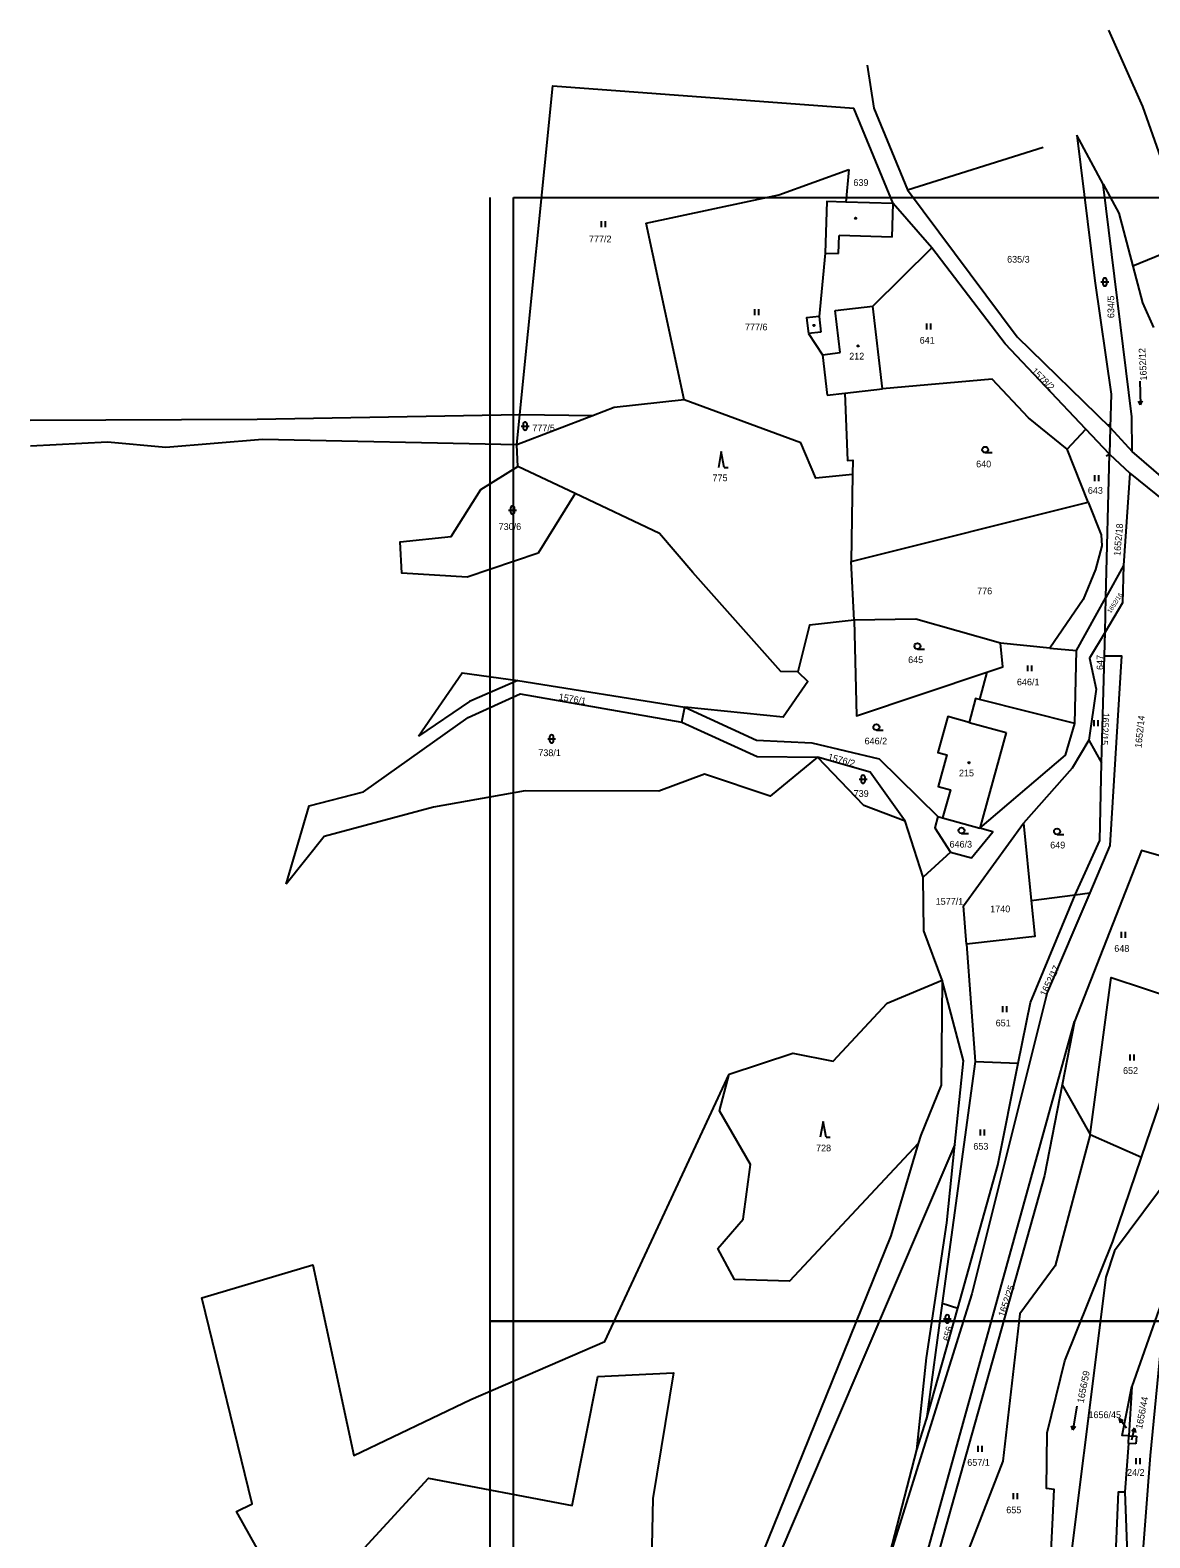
# Model space of a CAD drawing. Extents: x -553916 to -552953, y -1067470 to -1066637.
# Drawn here: x -553916.1 to -553633.4, y -1067154.7 to -1066774 of the extents above; entities that cross this region are included whole.
import ezdxf

# ---------------------------------------------------------------- set-up
doc = ezdxf.new("R2010")
doc.units = 0
for name, color, linetype in [('Hranice parcel', 7, 'Continuous'), ('Parcelní čísla', 7, 'Continuous'), ('Pop  PČ popisy', 7, 'Continuous'), ('Vnitřní kresba', 7, 'Continuous'), ('Vrstva 1', 7, 'Continuous'), ('Značky budov', 7, 'Continuous'), ('Značky kultur', 7, 'Continuous')]:
    doc.layers.add(name, color=color, linetype=linetype)

msp = doc.modelspace()

# ---------------------------------------------------------------- linework, layer by layer
at = {"layer": 'Hranice parcel'}
for p, q in [((-553698.19, -1066817.82), (-553708.14, -1066793.72)), ((-553694.61, -1066814.35), (-553660.35, -1066803.56)), ((-553645.19, -1066812.95), (-553651.89, -1066800.53)), ((-553727.1, -1066815.64), (-553709.46, -1066809.18)), ((-553709.46, -1066809.18), (-553710.17, -1066817.45)), ((-553760.56, -1066822.8), (-553727.1, -1066815.64)), ((-553698.19, -1066817.82), (-553710.17, -1066817.45)), ((-553688.48, -1066828.98), (-553698.19, -1066817.82)), ((-553750.96, -1066867.38), (-553760.56, -1066822.8)), ((-553623.67, -1066827.87), (-553637.71, -1066833.62)), ((-553710.42, -1066865.69), (-553700.89, -1066864.57)), ((-553714.89, -1066866.21), (-553710.42, -1066865.69)), ((-553793.21, -1066878.75), (-553792.44, -1066871.07)), ((-553773.88, -1066871.32), (-553793.21, -1066878.75)), ((-553792.44, -1066871.07), (-553773.88, -1066871.32)), ((-553654.33, -1066879.84), (-553649.57, -1066874.82)), ((-553643.58, -1066881.05), (-553649.57, -1066874.82)), ((-553643.41, -1066874.34), (-553637.93, -1066880.39)), ((-553792.95, -1066884.2), (-553793.21, -1066878.75)), ((-553648.98, -1066893.19), (-553654.33, -1066879.84)), ((-553629.4, -1066887.71), (-553637.93, -1066880.39)), ((-553778.5, -1066891.03), (-553792.95, -1066884.2)), ((-553644.51, -1066917.3), (-553643.58, -1066881.05)), ((-553643.58, -1066881.05), (-553638.51, -1066885.89)), ((-553708.48, -1066886.24), (-553708.86, -1066908.17)), ((-553638.51, -1066885.89), (-553640.1, -1066909.21)), ((-553708.86, -1066908.17), (-553648.98, -1066893.19)), ((-553708.1, -1066923.04), (-553708.86, -1066908.17)), ((-553640.1, -1066909.21), (-553644.51, -1066917.3)), ((-553651.92, -1066930.68), (-553644.51, -1066917.3)), ((-553644.74, -1066926.04), (-553644.51, -1066917.3)), ((-553644.89, -1066931.97), (-553644.74, -1066926.04)), ((-553658.66, -1066930.04), (-553671.16, -1066928.84)), ((-553658.66, -1066930.04), (-553651.92, -1066930.68)), ((-553652.33, -1066949.09), (-553651.92, -1066930.68)), ((-553645.59, -1066958.99), (-553644.89, -1066931.97)), ((-553674.58, -1066936.12), (-553676.4, -1066943.07)), ((-553793.02, -1066938.22), (-553750.82, -1066944.94)), ((-553751.58, -1066948.77), (-553750.82, -1066944.94)), ((-553652.33, -1066949.09), (-553676.4, -1066943.07)), ((-553648.85, -1066953.28), (-553645.59, -1066958.99)), ((-553690.64, -1066987.88), (-553695.17, -1066973.73)), ((-553686.98, -1066972.56), (-553685.74, -1066972.91)), ((-553685.74, -1066972.91), (-553676.37, -1066975.51)), ((-553665.3, -1066974.22), (-553663.36, -1066993.83)), ((-553683.73, -1066981.56), (-553690.64, -1066987.88)), ((-553663.36, -1066993.83), (-553652.32, -1066992.37)), ((-553652.32, -1066992.37), (-553648.57, -1066991.82)), ((-553679.73, -1067004.79), (-553677.51, -1067034.42)), ((-553652.47, -1067024.37), (-553655.53, -1067040.29)), ((-553677.51, -1067034.42), (-553685.85, -1067095.42)), ((-553677.51, -1067034.42), (-553666.64, -1067034.88)), ((-553655.53, -1067040.29), (-553648.45, -1067052.9)), ((-553682.64, -1067055.36), (-553736.85, -1067182.11)), ((-553648.45, -1067052.9), (-553635.52, -1067058.6)), ((-553642.79, -1067079.87), (-553635.52, -1067058.6)), ((-553685.85, -1067095.42), (-553689.85, -1067124.72)), ((-553689.85, -1067124.72), (-553681.91, -1067096.73)), ((-553685.85, -1067095.42), (-553681.91, -1067096.73)), ((-553637.98, -1067116.48), (-553638.7, -1067128.96)), ((-553692.26, -1067132.51), (-553689.85, -1067124.72)), ((-553638.81, -1067130.87), (-553639.7, -1067143.1)), ((-553638.81, -1067130.87), (-553638.7, -1067128.96)), ((-553636.94, -1067130.98), (-553638.81, -1067130.87)), ((-553638.7, -1067128.96), (-553636.8, -1067129.04)), ((-553636.8, -1067129.04), (-553636.94, -1067130.98)), ((-553699.64, -1067161.1), (-553692.26, -1067132.51)), ((-553639.7, -1067143.1), (-553638.95, -1067163.99))]:
    msp.add_line(p, q, dxfattribs=at)
for points in [[(-553643.88, -1066774.03), (-553635.29, -1066793.34), (-553625.66, -1066820.5)], [(-553704.82, -1066782.89), (-553703.1, -1066793.75), (-553694.61, -1066814.35)], [(-553792.44, -1066871.07), (-553784.13, -1066788.1), (-553708.14, -1066793.72)], [(-553651.89, -1066800.53), (-553647.31, -1066837.34), (-553643.19, -1066865.93), (-553643.41, -1066874.34)], [(-553694.61, -1066814.35), (-553666.95, -1066851.46), (-553643.41, -1066874.34)], [(-553637.93, -1066880.39), (-553637.95, -1066871.66), (-553645.19, -1066812.95)], [(-553645.19, -1066812.95), (-553641.24, -1066820.26), (-553637.71, -1066833.62)], [(-553710.17, -1066817.45), (-553715.01, -1066817.3), (-553715.41, -1066830.35), (-553716.91, -1066846.31), (-553720.09, -1066846.68), (-553719.63, -1066850.66)], [(-553700.89, -1066864.57), (-553703.32, -1066843.72), (-553688.48, -1066828.98)], [(-553649.57, -1066874.82), (-553669.94, -1066853.22), (-553688.48, -1066828.98)], [(-553637.71, -1066833.62), (-553635.67, -1066841.32), (-553635.29, -1066842.84), (-553632.51, -1066849.1)], [(-553719.63, -1066850.66), (-553716.09, -1066855.98), (-553714.89, -1066866.21)], [(-553654.33, -1066879.84), (-553664.06, -1066871.9), (-553673.22, -1066862.17), (-553700.89, -1066864.57)], [(-553750.96, -1066867.38), (-553768.66, -1066869.31), (-553773.88, -1066871.32)], [(-553708.48, -1066886.24), (-553717.76, -1066887.14), (-553721.5, -1066878.2), (-553750.96, -1066867.38)], [(-553710.42, -1066865.69), (-553709.75, -1066882.68), (-553708.42, -1066882.64), (-553708.48, -1066886.24)], [(-553916.1, -1066872.49), (-553858.75, -1066872.29), (-553792.44, -1066871.07)], [(-553793.21, -1066878.75), (-553857.42, -1066877.37), (-553881.82, -1066879.37), (-553896.57, -1066878.03), (-553915.98, -1066879.03)], [(-553778.5, -1066891.03), (-553787.89, -1066906.11), (-553805.77, -1066912.16), (-553822.27, -1066911.17), (-553822.69, -1066903.26), (-553809.84, -1066901.91), (-553802.35, -1066890.01), (-553792.95, -1066884.2)], [(-553638.51, -1066885.89), (-553629.69, -1066892.95), (-553626.61, -1066895.43)], [(-553722.33, -1066936.07), (-553726.59, -1066935.94), (-553748.79, -1066910.99), (-553757.18, -1066901.11), (-553778.5, -1066891.03)], [(-553648.98, -1066893.19), (-553645.71, -1066901.42), (-553645.52, -1066904.26), (-553647.18, -1066910.25), (-553650.27, -1066917.79), (-553658.66, -1066930.04)], [(-553640.1, -1066909.21), (-553640.34, -1066918.66), (-553644.74, -1066926.04)], [(-553708.1, -1066923.04), (-553719.33, -1066924.26), (-553722.33, -1066936.07)], [(-553671.16, -1066928.84), (-553692.53, -1066922.74), (-553708.1, -1066923.04)], [(-553708.1, -1066923.04), (-553707.52, -1066947.12), (-553674.58, -1066936.12)], [(-553644.74, -1066926.04), (-553648.66, -1066932.61), (-553646.94, -1066940.41), (-553648.85, -1066953.28)], [(-553674.58, -1066936.12), (-553670.5, -1066934.76), (-553671.16, -1066928.84)], [(-553644.89, -1066931.97), (-553640.62, -1066932.03), (-553643.49, -1066979.92), (-553648.57, -1066991.82)], [(-553818.03, -1066952.27), (-553807.07, -1066936.29), (-553793.02, -1066938.22)], [(-553722.33, -1066936.07), (-553719.8, -1066938.45), (-553726.01, -1066947.52), (-553750.82, -1066944.94)], [(-553793.02, -1066938.22), (-553805.16, -1066943.52), (-553818.03, -1066952.27)], [(-553851.45, -1066989.66), (-553845.69, -1066969.91), (-553831.91, -1066966.35), (-553805.48, -1066947.58), (-553792.42, -1066941.62), (-553751.58, -1066948.77)], [(-553750.82, -1066944.94), (-553732.69, -1066953.28), (-553718.72, -1066954.01), (-553701.74, -1066958), (-553686.98, -1066972.56)], [(-553676.4, -1066943.07), (-553677.43, -1066942.81), (-553679, -1066948.83), (-553684.45, -1066947.32), (-553686.97, -1066956.38), (-553684.65, -1066957.02), (-553686.87, -1066965.02), (-553683.79, -1066965.88), (-553685.74, -1066972.91)], [(-553751.58, -1066948.77), (-553732.58, -1066957.42), (-553717.29, -1066957.56)], [(-553676.37, -1066975.51), (-553654.76, -1066957.08), (-553652.33, -1066949.09)], [(-553648.85, -1066953.28), (-553653.03, -1066960.38), (-553665.3, -1066974.22)], [(-553717.29, -1066957.56), (-553729.27, -1066967.46), (-553745.82, -1066961.92), (-553757.37, -1066966.16), (-553791.09, -1066966.12), (-553814.24, -1066970.19), (-553841.88, -1066977.67), (-553851.45, -1066989.66)], [(-553695.17, -1066973.73), (-553705.64, -1066969.81), (-553717.29, -1066957.56)], [(-553695.17, -1066973.73), (-553704.05, -1066961.37), (-553717.29, -1066957.56)], [(-553652.32, -1066992.37), (-553646.09, -1066978.61), (-553645.59, -1066958.99)], [(-553686.98, -1066972.56), (-553687.7, -1066975.46), (-553683.73, -1066981.56)], [(-553683.73, -1066981.56), (-553678.45, -1066983.01), (-553673.1, -1066976.42), (-553676.37, -1066975.51)], [(-553679.73, -1067004.79), (-553680.45, -1066995.12), (-553665.3, -1066974.22)], [(-553627.02, -1066983.6), (-553635.52, -1066981.16), (-553652.47, -1067024.37)], [(-553623.32, -1066984.67), (-553619.63, -1066996.83), (-553619.56, -1067023.02), (-553621.7, -1067038.64), (-553627.75, -1067062.69), (-553642.34, -1067082.27), (-553644.52, -1067088.87), (-553655.73, -1067178.24), (-553657.73, -1067185.13), (-553660.17, -1067189.87)], [(-553685.87, -1067013.91), (-553690.5, -1067001.43), (-553690.64, -1066987.88)], [(-553648.57, -1066991.82), (-553659.32, -1067017.01), (-553678.4, -1067093.07), (-553699.64, -1067161.1)], [(-553663.36, -1066993.83), (-553662.49, -1067002.88), (-553679.73, -1067004.79)], [(-553666.64, -1067034.88), (-553663.56, -1067019.54), (-553652.32, -1066992.37)], [(-553648.45, -1067052.9), (-553643.22, -1067013.2), (-553625.87, -1067018.94)], [(-553739.65, -1067037.62), (-553723.52, -1067032.31), (-553713.35, -1067034.36), (-553699.72, -1067019.75), (-553685.87, -1067013.91)], [(-553685.87, -1067013.91), (-553686.09, -1067040.42), (-553691.28, -1067053.08), (-553691.88, -1067055.11)], [(-553682.64, -1067055.36), (-553680.47, -1067034.25), (-553685.87, -1067013.91)], [(-553635.52, -1067058.6), (-553624.9, -1067027.54), (-553625.87, -1067018.94)], [(-553695.94, -1067227.92), (-553697.09, -1067200.45), (-553693.46, -1067172.18), (-553652.47, -1067024.37)], [(-553681.91, -1067096.73), (-553671.8, -1067060.62), (-553666.64, -1067034.88)], [(-553856.98, -1067179.12), (-553855.63, -1067163.09), (-553864, -1067148.03), (-553860.02, -1067146.13), (-553872.73, -1067094.13), (-553844.72, -1067085.79), (-553834.37, -1067133.89), (-553804.82, -1067119.79), (-553771, -1067105.16), (-553739.65, -1067037.62)], [(-553691.88, -1067055.11), (-553724.41, -1067089.91), (-553738.29, -1067089.46), (-553742.48, -1067081.62), (-553736.1, -1067074.23), (-553734.28, -1067060.42), (-553742.1, -1067046.86), (-553739.65, -1067037.62)], [(-553655.53, -1067040.29), (-553660.05, -1067063.23), (-553688.55, -1067164.71), (-553692.38, -1067192.94), (-553695.94, -1067227.92)], [(-553691.88, -1067055.11), (-553698.79, -1067078.47), (-553744.69, -1067191.8)], [(-553692.26, -1067132.51), (-553689.81, -1067109.27), (-553684.68, -1067075.16), (-553682.64, -1067055.36)], [(-553648.45, -1067052.9), (-553657.29, -1067086.06), (-553666.21, -1067098.13), (-553670.52, -1067135.37), (-553684.51, -1067171.37), (-553689.91, -1067228.79)], [(-553660.17, -1067189.87), (-553659.36, -1067184.27), (-553658.56, -1067162.92), (-553658, -1067151.36), (-553657.6, -1067142.52), (-553659.52, -1067142.26), (-553659.32, -1067128.21), (-553654.86, -1067110.02), (-553642.79, -1067079.87)], [(-553629.28, -1067092.37), (-553631.12, -1067097.14), (-553637.98, -1067116.48)], [(-553629.28, -1067092.37), (-553633.37, -1067133.92), (-553635.66, -1067164.7)], [(-553852.6, -1067180), (-553815.54, -1067139.66), (-553779.26, -1067146.56), (-553772.79, -1067113.94), (-553753.66, -1067113.05), (-553758.92, -1067144.82), (-553759.49, -1067172.72), (-553744.69, -1067191.8)], [(-553638.7, -1067128.96), (-553640.44, -1067128.89), (-553637.98, -1067116.48)], [(-553643.28, -1067188.54), (-553641.31, -1067143.1), (-553639.7, -1067143.1)]]:
    msp.add_lwpolyline(points, dxfattribs=at)
at = {"layer": 'Pop  PČ popisy'}
for p, q in [((-553639.33, -1067126.98), (-553641.14, -1067124.58)), ((-553641.14, -1067124.58), (-553640.13, -1067125.08)), ((-553641.14, -1067124.58), (-553640.93, -1067125.68)), ((-553637.99, -1067129.93), (-553637.26, -1067127.02)), ((-553637.26, -1067127.02), (-553637.99, -1067127.87)), ((-553637.26, -1067127.02), (-553637.02, -1067128.11))]:
    msp.add_line(p, q, dxfattribs=at)
at = {"layer": 'Vnitřní kresba'}
for p, q in [((-553698.45, -1066826.31), (-553698.19, -1066817.82)), ((-553712.02, -1066830.45), (-553711.88, -1066825.9)), ((-553698.45, -1066826.31), (-553711.88, -1066825.9)), ((-553715.41, -1066830.35), (-553712.02, -1066830.45)), ((-553712.86, -1066844.83), (-553703.32, -1066843.72)), ((-553711.62, -1066855.46), (-553712.86, -1066844.83)), ((-553716.91, -1066846.31), (-553716.45, -1066850.28)), ((-553716.45, -1066850.28), (-553719.63, -1066850.66)), ((-553716.09, -1066855.98), (-553711.62, -1066855.46)), ((-553643.77, -1066873.41), (-553643.41, -1066874.34)), ((-553643.41, -1066874.34), (-553643.58, -1066881.05)), ((-553644.45, -1066881.55), (-553643.58, -1066881.05)), ((-553679, -1066948.83), (-553669.71, -1066951.41)), ((-553669.71, -1066951.41), (-553676.37, -1066975.51))]:
    msp.add_line(p, q, dxfattribs=at)
at = {"layer": 'Vrstva 1'}
for p, q in [((-553794.11, -1067410.27), (-553794.11, -1066816.27)), ((-553794.11, -1066816.27), (-552953.11, -1066816.27))]:
    msp.add_line(p, q, dxfattribs=at)
for points in [[(-553300, -1066816.27), (-553300, -1067100), (-553800, -1067100), (-553800, -1066816.27)], [(-553800, -1067410.27), (-553800, -1067100), (-553300, -1067100), (-553300, -1067410.27)]]:
    msp.add_lwpolyline(points, dxfattribs=at)
at = {"layer": 'Značky budov'}
for centre in [(-553707.7, -1066821.53), (-553718.22, -1066848.59), (-553707.07, -1066853.75), (-553679.08, -1066959.01)]:
    msp.add_circle(centre, 0.175, dxfattribs=at)
at = {"layer": 'Značky kultur'}
for p, q in [((-553771.87, -1066823.75), (-553771.87, -1066822.25)), ((-553770.87, -1066823.75), (-553770.87, -1066822.25)), ((-553645.79, -1066837.61), (-553643.79, -1066837.61)), ((-553645.29, -1066837.11), (-553645.29, -1066838.11)), ((-553644.29, -1066838.11), (-553644.29, -1066837.11)), ((-553733.13, -1066845.96), (-553733.13, -1066844.46)), ((-553732.13, -1066845.96), (-553732.13, -1066844.46)), ((-553689.71, -1066849.63), (-553689.71, -1066848.13)), ((-553688.71, -1066849.63), (-553688.71, -1066848.13)), ((-553635.98, -1066862.64), (-553635.77, -1066868.64)), ((-553635.77, -1066868.64), (-553636.31, -1066867.68)), ((-553635.77, -1066868.64), (-553635.31, -1066867.64)), ((-553792.14, -1066874), (-553790.14, -1066874)), ((-553791.64, -1066873.5), (-553791.64, -1066874.5)), ((-553790.64, -1066874.5), (-553790.64, -1066873.5)), ((-553741.61, -1066880.43), (-553742.36, -1066884.43)), ((-553740.86, -1066884.43), (-553741.61, -1066880.43)), ((-553675.01, -1066880.71), (-553673.26, -1066880.71)), ((-553740.86, -1066884.43), (-553739.86, -1066884.43)), ((-553647.32, -1066887.89), (-553647.32, -1066886.39)), ((-553646.32, -1066887.89), (-553646.32, -1066886.39)), ((-553795.31, -1066895.2), (-553793.31, -1066895.2)), ((-553794.81, -1066894.7), (-553794.81, -1066895.7)), ((-553793.81, -1066895.7), (-553793.81, -1066894.7)), ((-553692.1, -1066930.3), (-553690.35, -1066930.3)), ((-553664.19, -1066935.92), (-553664.19, -1066934.42)), ((-553663.19, -1066935.92), (-553663.19, -1066934.42)), ((-553647.46, -1066949.78), (-553647.46, -1066948.28)), ((-553646.46, -1066949.78), (-553646.46, -1066948.28)), ((-553784.95, -1066952.48), (-553784.95, -1066953.48)), ((-553783.95, -1066953.48), (-553783.95, -1066952.48)), ((-553702.46, -1066950.79), (-553700.71, -1066950.79)), ((-553785.45, -1066952.98), (-553783.45, -1066952.98)), ((-553706.83, -1066963.16), (-553704.83, -1066963.16)), ((-553706.33, -1066962.66), (-553706.33, -1066963.66)), ((-553705.33, -1066963.66), (-553705.33, -1066962.66)), ((-553680.98, -1066976.87), (-553679.23, -1066976.87)), ((-553656.85, -1066977.1), (-553655.1, -1066977.1)), ((-553640.58, -1067003.2), (-553640.58, -1067001.7)), ((-553639.58, -1067003.2), (-553639.58, -1067001.7)), ((-553670.54, -1067022.01), (-553670.54, -1067020.51)), ((-553669.54, -1067022.01), (-553669.54, -1067020.51)), ((-553638.37, -1067034.2), (-553638.37, -1067032.7)), ((-553637.37, -1067034.2), (-553637.37, -1067032.7)), ((-553715.92, -1067049.57), (-553716.67, -1067053.57)), ((-553715.17, -1067053.57), (-553715.92, -1067049.57)), ((-553676.17, -1067053.15), (-553676.17, -1067051.65)), ((-553675.17, -1067053.15), (-553675.17, -1067051.65)), ((-553715.17, -1067053.57), (-553714.17, -1067053.57)), ((-553685.56, -1067099.43), (-553683.56, -1067099.43)), ((-553685.06, -1067098.93), (-553685.06, -1067099.93)), ((-553684.06, -1067099.93), (-553684.06, -1067098.93)), ((-553651.89, -1067121.5), (-553652.83, -1067127.43)), ((-553652.83, -1067127.43), (-553653.17, -1067126.39)), ((-553652.83, -1067127.43), (-553652.18, -1067126.54)), ((-553676.73, -1067132.98), (-553676.73, -1067131.48)), ((-553675.73, -1067132.98), (-553675.73, -1067131.48)), ((-553636.91, -1067136.12), (-553636.91, -1067134.62)), ((-553635.91, -1067136.12), (-553635.91, -1067134.62)), ((-553667.85, -1067144.96), (-553667.85, -1067143.46)), ((-553666.85, -1067144.96), (-553666.85, -1067143.46))]:
    msp.add_line(p, q, dxfattribs=at)
for centre in [(-553675.01, -1066879.96), (-553692.1, -1066929.55), (-553702.46, -1066950.04), (-553680.98, -1066976.12), (-553656.85, -1066976.35)]:
    msp.add_circle(centre, 0.75, dxfattribs=at)
for centre, start, end in [((-553644.79, -1066837.11), 0, 180), ((-553644.79, -1066838.11), 180, 359.9879), ((-553791.14, -1066873.5), 0, 180), ((-553791.14, -1066874.5), 180, 359.9879), ((-553794.31, -1066894.7), 0, 180), ((-553794.31, -1066895.7), 180, 359.9879), ((-553784.45, -1066952.48), 0, 180), ((-553784.45, -1066953.48), 180, 359.9879), ((-553705.83, -1066962.66), 0, 180), ((-553705.83, -1066963.66), 180, 359.9879), ((-553684.56, -1067098.93), 0, 180), ((-553684.56, -1067099.93), 180, 359.9879)]:
    msp.add_arc(centre, 0.5, start, end, dxfattribs=at)

# ---------------------------------------------------------------- texts
at = {"layer": 'Parcelní čísla'}
for s, p in [('639', (-553708.26, -1066813.36)), ('777/2', (-553775.03, -1066827.6)), ('635/3', (-553669.46, -1066832.73)), ('777/6', (-553735.64, -1066849.83)), ('641', (-553691.53, -1066853.18)), ('212', (-553709.32, -1066857.2)), ('777/5', (-553789.32, -1066875.32)), ('640', (-553677.28, -1066884.42)), ('775', (-553743.83, -1066887.91)), ('643', (-553649.07, -1066891.09)), ('730/6', (-553797.83, -1066900.23)), ('776', (-553677.03, -1066916.48)), ('645', (-553694.44, -1066933.85)), ('646/1', (-553666.98, -1066939.47)), ('646/2', (-553705.44, -1066954.37)), ('738/1', (-553787.81, -1066957.34)), ('215', (-553681.62, -1066962.45)), ('739', (-553708.2, -1066967.62)), ('646/3', (-553684, -1066980.43)), ('649', (-553658.58, -1066980.65)), ('1577/1', (-553687.49, -1066994.87)), ('1740', (-553673.72, -1066996.76)), ('648', (-553642.4, -1067006.75)), ('651', (-553672.35, -1067025.56)), ('652', (-553640.19, -1067037.58)), ('728', (-553717.69, -1067057.12)), ('653', (-553677.98, -1067056.7)), ('1656/45', (-553648.92, -1067124.49)), ('657/1', (-553679.52, -1067136.53)), ('24/2', (-553639.18, -1067139.06)), ('655', (-553669.67, -1067148.51))]:
    msp.add_text(s, height=1.7, dxfattribs=at).set_placement(p)
for s, height, rotation, p in [('634/5', 1.7, 90, (-553642.41, -1066846.74)), ('1652/12', 1.7, 93, (-553634.14, -1066862.46)), ('1578/2', 1.7, 316, (-553663.5, -1066860.33)), ('1652/18', 1.7, 85, (-553640.88, -1066906.84)), ('1652/16', 1.14, 57, (-553643.32, -1066921.35)), ('647', 1.7, 90, (-553645.15, -1066935.58)), ('1576/1', 1.7, 350, (-553782.76, -1066943.13)), ('1652/15', 1.7, 267, (-553645.34, -1066946.31)), ('1652/14', 1.7, 84, (-553635.53, -1066955.34)), ('1576/2', 1.7, 345, (-553714.84, -1066958.27)), ('1652/17', 1.7, 64, (-553659.73, -1067018.1)), ('1652/25', 1.7, 71, (-553670.16, -1067099.05)), ('656', 1.7, 77, (-553684.01, -1067105.17)), ('1656/59', 1.7, 79, (-553650.14, -1067120.79)), ('1656/44', 1.7, 79, (-553635.39, -1067127.33))]:
    msp.add_text(s, height=height, rotation=rotation, dxfattribs=at).set_placement(p)

doc.saveas('drawing.dxf')
